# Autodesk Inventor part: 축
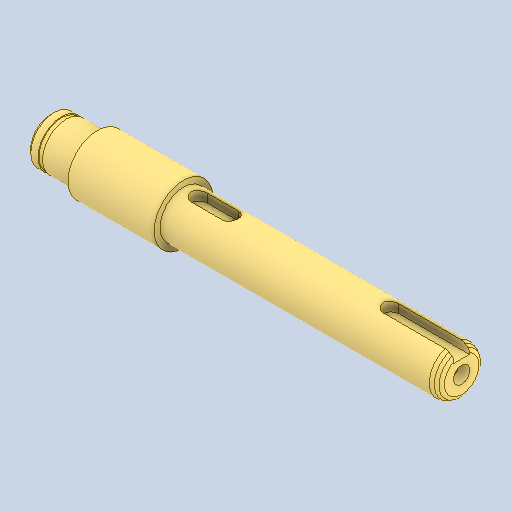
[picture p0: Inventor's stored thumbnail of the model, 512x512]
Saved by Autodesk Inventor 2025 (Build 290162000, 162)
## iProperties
Created: 2026-07
Part Number: 축
Material: 강철, 탄소
Document SubType Name: Modeling
Designer: KDI
Density: 7.85 g/cm^3
Appearance: 기본값
Author: jhkim
Sending System: Autodesk Inventor 2027
Preprocessor: ST-DEVELOPER v20.1
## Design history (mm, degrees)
feature "솔리드1"
node "솔리드2"
